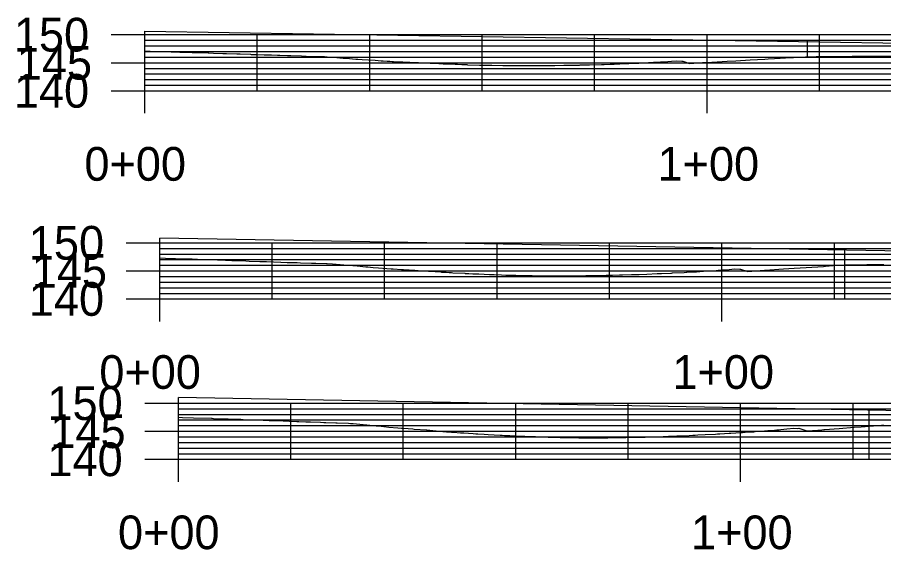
# Model space of a CAD drawing. Extents: x 1556849 to 1559393, y 1802592 to 1804749.
# Drawn here: x 1559139.6 to 1559293.7, y 1802892.3 to 1802987.1 of the extents above; entities that cross this region are included whole.
import ezdxf

# ---------------------------------------------------------------- set-up
doc = ezdxf.new("R2010")
doc.units = 0
for name, color, linetype in [('R_Axis', 7, 'Continuous'), ('R_Axis Annot', 7, 'Continuous'), ('R_Fin Surface', 7, 'Continuous'), ('R_Grid', 7, 'Continuous'), ('R_Proposed Const Limits_Hand', 7, 'Continuous'), ('R_Vert Alg Annot', 7, 'Continuous')]:
    doc.layers.add(name, color=color, linetype=linetype)

msp = doc.modelspace()

# ---------------------------------------------------------------- linework, layer by layer
at = {"layer": 'R_Axis'}
for p, q in [((1559162.3, 1802974.01), (1559162.3, 1802984.01)), ((1559162.3, 1802974.01), (1559362.3, 1802974.01)), ((1559164.95, 1802936.96), (1559164.95, 1802946.96)), ((1559164.95, 1802936.96), (1559364.95, 1802936.96)), ((1559168.27, 1802908.42), (1559168.27, 1802918.42)), ((1559168.27, 1802908.42), (1559368.27, 1802908.42))]:
    msp.add_line(p, q, dxfattribs=at)
at = {"layer": 'R_Fin Surface'}
for points in [[(1559162.3, 1802981.14), (1559163.26, 1802981.1), (1559164.85, 1802981.04), (1559165.92, 1802981.01), (1559166.05, 1802981.01), (1559166.3, 1802981), (1559167, 1802980.98), (1559168.54, 1802980.92), (1559170.73, 1802980.85), (1559171.12, 1802980.84), (1559171.17, 1802980.84), (1559171.49, 1802980.83), (1559173.59, 1802980.76), (1559173.67, 1802980.75), (1559174.51, 1802980.73), (1559176.18, 1802980.67), (1559176.21, 1802980.67), (1559176.54, 1802980.66), (1559176.81, 1802980.65), (1559178.65, 1802980.59), (1559179.28, 1802980.57), (1559181.1, 1802980.51), (1559181.23, 1802980.5), (1559181.47, 1802980.5), (1559182.32, 1802980.47), (1559183.52, 1802980.43), (1559184.83, 1802980.39), (1559185.92, 1802980.36), (1559186.14, 1802980.35), (1559186.28, 1802980.35), (1559187.66, 1802980.3), (1559188.29, 1802980.28), (1559190.19, 1802980.22), (1559190.63, 1802980.21), (1559190.94, 1802980.2), (1559191, 1802980.2), (1559192.83, 1802980.15), (1559192.96, 1802980.14), (1559194.24, 1802980.11), (1559195.26, 1802980.02), (1559195.29, 1802980.02), (1559195.63, 1802979.99), (1559195.83, 1802979.98), (1559197.55, 1802979.84), (1559198.11, 1802979.8), (1559199.82, 1802979.67), (1559199.95, 1802979.66), (1559200.18, 1802979.65), (1559200.95, 1802979.59), (1559202.07, 1802979.52), (1559203.24, 1802979.44), (1559204.31, 1802979.37), (1559204.53, 1802979.36), (1559204.68, 1802979.35), (1559205.42, 1802979.3), (1559205.87, 1802979.28), (1559206.31, 1802979.25), (1559206.54, 1802979.24), (1559208.16, 1802979.16), (1559208.75, 1802979.13), (1559209.03, 1802979.11), (1559209.12, 1802979.11), (1559209.35, 1802979.1), (1559209.41, 1802979.09), (1559210.06, 1802979.06), (1559210.22, 1802979.06), (1559210.84, 1802979.03), (1559210.95, 1802979.03), (1559213.06, 1802978.94), (1559213.15, 1802978.94), (1559213.52, 1802978.93), (1559213.52, 1802978.93), (1559213.84, 1802978.92), (1559215.34, 1802978.84), (1559216.18, 1802978.8), (1559217.52, 1802978.74), (1559217.75, 1802978.73), (1559217.89, 1802978.73), (1559218.69, 1802978.7), (1559218.98, 1802978.68), (1559219.56, 1802978.67), (1559219.69, 1802978.66), (1559221.84, 1802978.6), (1559221.86, 1802978.6), (1559221.95, 1802978.6), (1559222.24, 1802978.6), (1559222.24, 1802978.6), (1559223.94, 1802978.56), (1559224.03, 1802978.56), (1559226, 1802978.53), (1559226.19, 1802978.53), (1559226.54, 1802978.52), (1559226.58, 1802978.52), (1559228.16, 1802978.51), (1559228.35, 1802978.51), (1559230.26, 1802978.51), (1559230.52, 1802978.51), (1559230.87, 1802978.51), (1559230.91, 1802978.51), (1559232.47, 1802978.51), (1559232.68, 1802978.51), (1559234.61, 1802978.53), (1559234.85, 1802978.53), (1559235.21, 1802978.54), (1559235.25, 1802978.54), (1559236.85, 1802978.56), (1559237.02, 1802978.56), (1559239.03, 1802978.59), (1559239.2, 1802978.6), (1559239.58, 1802978.6), (1559239.61, 1802978.6), (1559239.74, 1802978.61), (1559241.38, 1802978.65), (1559243.51, 1802978.7), (1559243.57, 1802978.71), (1559243.98, 1802978.72), (1559243.99, 1802978.72), (1559245.05, 1802978.76), (1559245.73, 1802978.78), (1559245.77, 1802978.78), (1559247.78, 1802978.86), (1559247.98, 1802978.86), (1559248.36, 1802978.88), (1559248.4, 1802978.88), (1559249.9, 1802978.95), (1559250.19, 1802978.96), (1559251.89, 1802979.05), (1559252.43, 1802979.07), (1559252.75, 1802979.09), (1559252.86, 1802979.1), (1559253.65, 1802979.14), (1559253.99, 1802979.16), (1559254.44, 1802979.19), (1559254.67, 1802979.2), (1559255.97, 1802979.29), (1559256.93, 1802979.36), (1559257.84, 1802979.3), (1559257.98, 1802979.31), (1559259.2, 1802978.89), (1559259.2, 1802978.89), (1559261.5, 1802979.03), (1559261.77, 1802979.04), (1559262.22, 1802979.07), (1559262.29, 1802979.07), (1559265.85, 1802979.28), (1559267.42, 1802979.37), (1559269.98, 1802979.51), (1559272.56, 1802979.66), (1559273.15, 1802979.69), (1559274.3, 1802979.76), (1559277.26, 1802979.93), (1559277.7, 1802979.96), (1559279.83, 1802980.08), (1559281.72, 1802980.1), (1559282.84, 1802980.11), (1559284.95, 1802980.13), (1559287.97, 1802980.15), (1559288.18, 1802980.16), (1559288.54, 1802980.16), (1559292.63, 1802980.17), (1559293.11, 1802980.18), (1559297.22, 1802980.2)], [(1559164.95, 1802944.27), (1559165.96, 1802944.24), (1559167.39, 1802944.19), (1559167.53, 1802944.19), (1559167.75, 1802944.18), (1559169.32, 1802944.12), (1559170.05, 1802944.1), (1559170.72, 1802944.08), (1559172.66, 1802944.01), (1559172.72, 1802944.01), (1559173.02, 1802943.99), (1559173.34, 1802943.99), (1559175.24, 1802943.92), (1559176.63, 1802943.87), (1559177.78, 1802943.83), (1559177.81, 1802943.83), (1559178.14, 1802943.81), (1559178.35, 1802943.81), (1559180.29, 1802943.73), (1559180.87, 1802943.71), (1559182.76, 1802943.65), (1559182.88, 1802943.64), (1559183.12, 1802943.63), (1559183.95, 1802943.61), (1559185.21, 1802943.56), (1559186.5, 1802943.52), (1559187.62, 1802943.48), (1559187.83, 1802943.48), (1559187.97, 1802943.47), (1559189.37, 1802943.43), (1559190.01, 1802943.41), (1559191.93, 1802943.34), (1559192.37, 1802943.33), (1559192.67, 1802943.32), (1559192.72, 1802943.32), (1559194.6, 1802943.26), (1559194.71, 1802943.25), (1559195.68, 1802943.22), (1559197.02, 1802943.1), (1559197.06, 1802943.09), (1559197.37, 1802943.06), (1559197.68, 1802943.04), (1559199.32, 1802942.89), (1559200.06, 1802942.83), (1559201.59, 1802942.7), (1559201.75, 1802942.69), (1559201.95, 1802942.67), (1559202.93, 1802942.59), (1559203.85, 1802942.52), (1559205.32, 1802942.41), (1559206.09, 1802942.35), (1559206.35, 1802942.33), (1559206.45, 1802942.33), (1559207.94, 1802942.22), (1559208.32, 1802942.2), (1559210.34, 1802942.07), (1559210.53, 1802942.05), (1559210.86, 1802942.03), (1559210.89, 1802942.03), (1559212.39, 1802941.94), (1559212.73, 1802941.92), (1559212.91, 1802941.9), (1559214.92, 1802941.77), (1559215.06, 1802941.76), (1559215.28, 1802941.74), (1559215.88, 1802941.71), (1559216.45, 1802941.67), (1559216.87, 1802941.65), (1559217.1, 1802941.64), (1559219.21, 1802941.53), (1559219.27, 1802941.52), (1559219.41, 1802941.52), (1559219.63, 1802941.51), (1559219.63, 1802941.51), (1559219.91, 1802941.49), (1559219.92, 1802941.49), (1559220.65, 1802941.46), (1559220.72, 1802941.46), (1559220.78, 1802941.46), (1559221.43, 1802941.42), (1559221.73, 1802941.41), (1559223.59, 1802941.33), (1559223.68, 1802941.32), (1559223.96, 1802941.31), (1559224.46, 1802941.29), (1559225.74, 1802941.25), (1559226.5, 1802941.22), (1559227.89, 1802941.18), (1559228.04, 1802941.17), (1559228.26, 1802941.17), (1559228.71, 1802941.15), (1559229.34, 1802941.14), (1559229.72, 1802941.13), (1559230.04, 1802941.13), (1559231.18, 1802941.11), (1559232.18, 1802941.1), (1559232.38, 1802941.09), (1559232.56, 1802941.09), (1559233.5, 1802941.08), (1559234.32, 1802941.08), (1559235.48, 1802941.08), (1559236.47, 1802941.08), (1559236.68, 1802941.08), (1559236.85, 1802941.08), (1559237.85, 1802941.08), (1559238.61, 1802941.09), (1559239.88, 1802941.1), (1559240.76, 1802941.11), (1559241, 1802941.11), (1559241.15, 1802941.12), (1559242.26, 1802941.14), (1559242.91, 1802941.15), (1559244.36, 1802941.18), (1559245.07, 1802941.19), (1559245.35, 1802941.2), (1559245.47, 1802941.2), (1559246.74, 1802941.24), (1559247.24, 1802941.25), (1559248.89, 1802941.3), (1559249.41, 1802941.31), (1559249.73, 1802941.32), (1559249.82, 1802941.33), (1559250.22, 1802941.34), (1559251.59, 1802941.39), (1559253.44, 1802941.47), (1559253.78, 1802941.48), (1559254.15, 1802941.5), (1559254.2, 1802941.5), (1559255.84, 1802941.58), (1559255.98, 1802941.58), (1559256.13, 1802941.59), (1559258.2, 1802941.7), (1559258.21, 1802941.7), (1559258.63, 1802941.72), (1559258.63, 1802941.72), (1559258.73, 1802941.73), (1559260.29, 1802941.82), (1559260.43, 1802941.82), (1559262.26, 1802941.94), (1559262.67, 1802941.96), (1559263.02, 1802941.99), (1559263.12, 1802941.99), (1559263.94, 1802942.05), (1559264.25, 1802942.07), (1559264.72, 1802942.11), (1559264.94, 1802942.12), (1559266.26, 1802942.23), (1559267.21, 1802942.31), (1559268.11, 1802942.27), (1559268.26, 1802942.28), (1559269.4, 1802941.9), (1559269.4, 1802941.9), (1559269.51, 1802941.87), (1559271.74, 1802942.02), (1559272.11, 1802942.04), (1559272.53, 1802942.07), (1559272.63, 1802942.08), (1559275.91, 1802942.3), (1559277.82, 1802942.42), (1559279.92, 1802942.57), (1559283.01, 1802942.77), (1559283.37, 1802942.8), (1559284.76, 1802942.89), (1559286.82, 1802943.03), (1559287.76, 1802943.04), (1559288.2, 1802943.04), (1559290.7, 1802943.07), (1559293.39, 1802943.1), (1559293.76, 1802943.1)], [(1559168.27, 1802915.91), (1559168.97, 1802915.89), (1559170.95, 1802915.83), (1559174.17, 1802915.72), (1559174.26, 1802915.72), (1559174.52, 1802915.71), (1559176.46, 1802915.64), (1559176.79, 1802915.63), (1559177.1, 1802915.62), (1559179.38, 1802915.54), (1559179.38, 1802915.54), (1559179.73, 1802915.53), (1559179.78, 1802915.53), (1559181.92, 1802915.44), (1559182.27, 1802915.43), (1559184.43, 1802915.34), (1559184.52, 1802915.34), (1559184.78, 1802915.33), (1559185.45, 1802915.31), (1559186.91, 1802915.25), (1559188.02, 1802915.21), (1559189.35, 1802915.16), (1559189.54, 1802915.15), (1559189.7, 1802915.15), (1559190.96, 1802915.1), (1559191.77, 1802915.07), (1559193.55, 1802915.01), (1559194.15, 1802914.99), (1559194.43, 1802914.98), (1559194.5, 1802914.98), (1559196.29, 1802914.92), (1559196.51, 1802914.91), (1559198.51, 1802914.85), (1559198.85, 1802914.81), (1559198.86, 1802914.81), (1559199.19, 1802914.78), (1559199.34, 1802914.77), (1559201.16, 1802914.59), (1559201.81, 1802914.53), (1559203.45, 1802914.38), (1559203.6, 1802914.36), (1559203.79, 1802914.35), (1559204.79, 1802914.26), (1559205.72, 1802914.17), (1559207.27, 1802914.04), (1559207.97, 1802913.98), (1559208.23, 1802913.96), (1559208.32, 1802913.95), (1559209.95, 1802913.82), (1559210.21, 1802913.8), (1559212.38, 1802913.64), (1559212.43, 1802913.63), (1559212.43, 1802913.63), (1559212.77, 1802913.6), (1559212.97, 1802913.59), (1559214.63, 1802913.44), (1559215.98, 1802913.34), (1559216.83, 1802913.27), (1559217.1, 1802913.25), (1559217.17, 1802913.24), (1559218.42, 1802913.15), (1559219.01, 1802913.11), (1559220.69, 1802912.99), (1559221.18, 1802912.96), (1559221.43, 1802912.94), (1559221.53, 1802912.94), (1559222.65, 1802912.87), (1559223.34, 1802912.83), (1559224.41, 1802912.77), (1559225.49, 1802912.71), (1559225.64, 1802912.7), (1559225.84, 1802912.69), (1559226.3, 1802912.67), (1559226.99, 1802912.64), (1559227.22, 1802912.63), (1559227.63, 1802912.61), (1559228.29, 1802912.58), (1559229.77, 1802912.52), (1559229.87, 1802912.52), (1559230.13, 1802912.51), (1559230.21, 1802912.51), (1559230.41, 1802912.5), (1559230.61, 1802912.5), (1559231.2, 1802912.48), (1559231.74, 1802912.46), (1559231.91, 1802912.45), (1559233.58, 1802912.4), (1559234.04, 1802912.39), (1559234.33, 1802912.38), (1559234.4, 1802912.37), (1559235.83, 1802912.34), (1559236.17, 1802912.33), (1559237.88, 1802912.3), (1559238.3, 1802912.29), (1559238.6, 1802912.28), (1559238.67, 1802912.28), (1559239.52, 1802912.27), (1559239.73, 1802912.27), (1559239.86, 1802912.27), (1559240.42, 1802912.27), (1559240.86, 1802912.26), (1559242.55, 1802912.26), (1559242.65, 1802912.26), (1559242.93, 1802912.26), (1559243.38, 1802912.27), (1559244.68, 1802912.27), (1559245.32, 1802912.28), (1559246.82, 1802912.3), (1559246.95, 1802912.3), (1559247.2, 1802912.3), (1559247.85, 1802912.32), (1559248.96, 1802912.34), (1559249.86, 1802912.36), (1559251.1, 1802912.39), (1559251.29, 1802912.39), (1559251.49, 1802912.4), (1559252.37, 1802912.43), (1559253.26, 1802912.45), (1559254.47, 1802912.5), (1559255.42, 1802912.53), (1559255.66, 1802912.54), (1559255.82, 1802912.54), (1559256.95, 1802912.59), (1559257.58, 1802912.61), (1559259.12, 1802912.68), (1559259.76, 1802912.7), (1559260.07, 1802912.72), (1559260.17, 1802912.72), (1559260.65, 1802912.75), (1559261.96, 1802912.81), (1559263.79, 1802912.91), (1559264.16, 1802912.93), (1559264.53, 1802912.95), (1559264.58, 1802912.95), (1559266.25, 1802913.05), (1559266.38, 1802913.06), (1559266.51, 1802913.07), (1559268.32, 1802913.18), (1559268.58, 1802913.2), (1559268.61, 1802913.2), (1559269.03, 1802913.23), (1559269.05, 1802913.23), (1559270.6, 1802913.34), (1559270.86, 1802913.36), (1559272.53, 1802913.48), (1559273.13, 1802913.53), (1559273.44, 1802913.55), (1559273.58, 1802913.56), (1559274.3, 1802913.62), (1559274.73, 1802913.66), (1559275.13, 1802913.69), (1559275.42, 1802913.72), (1559276.5, 1802913.82), (1559277.74, 1802913.94), (1559278.37, 1802913.92), (1559278.6, 1802913.94), (1559279.34, 1802913.71), (1559279.34, 1802913.71), (1559280.07, 1802913.48), (1559282, 1802913.63), (1559282.69, 1802913.68), (1559283.05, 1802913.71), (1559283.22, 1802913.72), (1559285.82, 1802913.92), (1559288.47, 1802914.12), (1559289.73, 1802914.22), (1559293.32, 1802914.49), (1559293.54, 1802914.49), (1559293.72, 1802914.49)]]:
    msp.add_lwpolyline(points, dxfattribs=at)
at = {"layer": 'R_Grid'}
for p, q in [((1559156.3, 1802984.01), (1559162.3, 1802984.01)), ((1559156.3, 1802984.01), (1559162.3, 1802984.01)), ((1559162.3, 1802984.01), (1559362.3, 1802984.01)), ((1559162.3, 1802984.01), (1559362.3, 1802984.01)), ((1559182.3, 1802974.01), (1559182.3, 1802984.01)), ((1559202.3, 1802974.01), (1559202.3, 1802984.01)), ((1559222.3, 1802974.01), (1559222.3, 1802984.01)), ((1559242.3, 1802974.01), (1559242.3, 1802984.01)), ((1559262.3, 1802974.01), (1559262.3, 1802984.01)), ((1559282.3, 1802974.01), (1559282.3, 1802984.01)), ((1559162.3, 1802983.01), (1559165.3, 1802983.01)), ((1559162.3, 1802983.01), (1559362.3, 1802983.01)), ((1559162.3, 1802982.01), (1559165.3, 1802982.01)), ((1559162.3, 1802982.01), (1559362.3, 1802982.01)), ((1559162.3, 1802981.01), (1559165.3, 1802981.01)), ((1559162.3, 1802981.01), (1559362.3, 1802981.01)), ((1559156.3, 1802979.01), (1559162.3, 1802979.01)), ((1559162.3, 1802980.01), (1559165.3, 1802980.01)), ((1559162.3, 1802980.01), (1559362.3, 1802980.01)), ((1559162.3, 1802979.01), (1559362.3, 1802979.01)), ((1559162.3, 1802978.01), (1559165.3, 1802978.01)), ((1559162.3, 1802978.01), (1559362.3, 1802978.01)), ((1559162.3, 1802977.01), (1559165.3, 1802977.01)), ((1559162.3, 1802977.01), (1559362.3, 1802977.01)), ((1559162.3, 1802976.01), (1559165.3, 1802976.01)), ((1559162.3, 1802976.01), (1559362.3, 1802976.01)), ((1559162.3, 1802975.01), (1559165.3, 1802975.01)), ((1559162.3, 1802975.01), (1559362.3, 1802975.01)), ((1559156.3, 1802974.01), (1559162.3, 1802974.01)), ((1559162.3, 1802970.01), (1559162.3, 1802974.01)), ((1559262.3, 1802970.01), (1559262.3, 1802974.01)), ((1559158.95, 1802946.96), (1559164.95, 1802946.96)), ((1559158.95, 1802946.96), (1559164.95, 1802946.96)), ((1559164.95, 1802946.96), (1559364.95, 1802946.96)), ((1559164.95, 1802946.96), (1559364.95, 1802946.96)), ((1559184.95, 1802936.96), (1559184.95, 1802946.96)), ((1559204.95, 1802936.96), (1559204.95, 1802946.96)), ((1559224.95, 1802936.96), (1559224.95, 1802946.96)), ((1559244.95, 1802936.96), (1559244.95, 1802946.96)), ((1559264.95, 1802936.96), (1559264.95, 1802946.96)), ((1559284.95, 1802936.96), (1559284.95, 1802946.96)), ((1559164.95, 1802945.96), (1559167.95, 1802945.96)), ((1559164.95, 1802945.96), (1559364.95, 1802945.96)), ((1559164.95, 1802944.96), (1559167.95, 1802944.96)), ((1559164.95, 1802944.96), (1559364.95, 1802944.96)), ((1559164.95, 1802943.96), (1559167.95, 1802943.96)), ((1559164.95, 1802943.96), (1559364.95, 1802943.96)), ((1559158.95, 1802941.96), (1559164.95, 1802941.96)), ((1559164.95, 1802942.96), (1559167.95, 1802942.96)), ((1559164.95, 1802942.96), (1559364.95, 1802942.96)), ((1559164.95, 1802941.96), (1559364.95, 1802941.96)), ((1559164.95, 1802940.96), (1559167.95, 1802940.96)), ((1559164.95, 1802940.96), (1559364.95, 1802940.96)), ((1559164.95, 1802939.96), (1559167.95, 1802939.96)), ((1559164.95, 1802939.96), (1559364.95, 1802939.96)), ((1559164.95, 1802938.96), (1559167.95, 1802938.96)), ((1559164.95, 1802938.96), (1559364.95, 1802938.96)), ((1559164.95, 1802937.96), (1559167.95, 1802937.96)), ((1559164.95, 1802937.96), (1559364.95, 1802937.96)), ((1559158.95, 1802936.96), (1559164.95, 1802936.96)), ((1559164.95, 1802932.96), (1559164.95, 1802936.96)), ((1559264.95, 1802932.96), (1559264.95, 1802936.96)), ((1559162.27, 1802918.42), (1559168.27, 1802918.42)), ((1559162.27, 1802918.42), (1559168.27, 1802918.42)), ((1559168.27, 1802918.42), (1559368.27, 1802918.42)), ((1559168.27, 1802918.42), (1559368.27, 1802918.42)), ((1559168.27, 1802917.42), (1559171.27, 1802917.42)), ((1559168.27, 1802917.42), (1559368.27, 1802917.42)), ((1559188.27, 1802908.42), (1559188.27, 1802918.42)), ((1559208.27, 1802908.42), (1559208.27, 1802918.42)), ((1559228.27, 1802908.42), (1559228.27, 1802918.42)), ((1559248.27, 1802908.42), (1559248.27, 1802918.42)), ((1559268.27, 1802908.42), (1559268.27, 1802918.42)), ((1559288.27, 1802908.42), (1559288.27, 1802918.42)), ((1559168.27, 1802916.42), (1559171.27, 1802916.42)), ((1559168.27, 1802916.42), (1559368.27, 1802916.42)), ((1559168.27, 1802915.42), (1559171.27, 1802915.42)), ((1559168.27, 1802915.42), (1559368.27, 1802915.42)), ((1559168.27, 1802914.42), (1559171.27, 1802914.42)), ((1559168.27, 1802914.42), (1559368.27, 1802914.42)), ((1559162.27, 1802913.42), (1559168.27, 1802913.42)), ((1559168.27, 1802913.42), (1559368.27, 1802913.42)), ((1559168.27, 1802912.42), (1559171.27, 1802912.42)), ((1559168.27, 1802912.42), (1559368.27, 1802912.42)), ((1559168.27, 1802911.42), (1559171.27, 1802911.42)), ((1559168.27, 1802911.42), (1559368.27, 1802911.42)), ((1559168.27, 1802910.42), (1559171.27, 1802910.42)), ((1559168.27, 1802910.42), (1559368.27, 1802910.42)), ((1559168.27, 1802909.42), (1559171.27, 1802909.42)), ((1559168.27, 1802909.42), (1559368.27, 1802909.42)), ((1559162.27, 1802908.42), (1559168.27, 1802908.42)), ((1559168.27, 1802904.42), (1559168.27, 1802908.42)), ((1559268.27, 1802904.42), (1559268.27, 1802908.42))]:
    msp.add_line(p, q, dxfattribs=at)
at = {"layer": 'R_Proposed Const Limits_Hand'}
for p, q in [((1559162.3, 1802981.14), (1559162.3, 1802984.64)), ((1559162.3, 1802984.64), (1559310.3, 1802982.26)), ((1559280.17, 1802980.09), (1559280.17, 1802983.09)), ((1559164.95, 1802944.27), (1559164.95, 1802947.77)), ((1559312.95, 1802945.21), (1559164.95, 1802947.77)), ((1559286.82, 1802936.96), (1559286.82, 1802946.03)), ((1559164.95, 1802936.96), (1559286.82, 1802936.96)), ((1559168.27, 1802915.91), (1559168.27, 1802919.41)), ((1559316.27, 1802916.67), (1559168.27, 1802919.41)), ((1559291.14, 1802908.42), (1559291.14, 1802917.32)), ((1559168.27, 1802908.42), (1559291.14, 1802908.42))]:
    msp.add_line(p, q, dxfattribs=at)

# ---------------------------------------------------------------- texts
at = {"layer": 'R_Axis'}
for s, p in [('150', (1559139, 1802981.01)), ('150', (1559139, 1802981.01)), ('145', (1559139.52, 1802976.01)), ('140', (1559139, 1802971.01)), ('150', (1559141.66, 1802943.96)), ('150', (1559141.66, 1802943.96)), ('145', (1559142.18, 1802938.96)), ('140', (1559141.66, 1802933.96)), ('150', (1559144.97, 1802915.42)), ('150', (1559144.97, 1802915.42)), ('145', (1559145.49, 1802910.42)), ('140', (1559144.97, 1802905.42))]:
    msp.add_text(s, height=6, dxfattribs=at).set_placement(p)
at = {"layer": 'R_Axis Annot'}
for p in [(1559162.3, 1802974.01), (1559164.95, 1802936.96), (1559168.27, 1802908.42)]:
    msp.add_text('-', height=0.0001, dxfattribs=at).set_placement(p)
at = {"layer": 'R_Vert Alg Annot'}
for s, p in [('0+00', (1559151.55, 1802958.01)), ('1+00', (1559253.49, 1802958.01)), ('0+00', (1559154.2, 1802920.96)), ('1+00', (1559256.14, 1802920.96)), ('0+00', (1559157.52, 1802892.42)), ('1+00', (1559259.45, 1802892.42))]:
    msp.add_text(s, height=6, dxfattribs=at).set_placement(p)

doc.saveas('drawing.dxf')
